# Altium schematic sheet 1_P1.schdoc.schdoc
size 309 x 223 mm; Symbol: Sheet-Symbol_A4; Device: Sheet-Symbol_A4; Company: ROMASZEWSKI; Drawed: ROMASZEWSKI; Reviewed: EasyEDA Pro; Version: V0.1; Page Size: A4; @Project Name: stm32wb5mmg01; @Page Count: 1; @Update Date: 2023-11-05; @Create Date: 2023-10-26; @Schematic Name: Shield MB STM32WB55; Part Number: JLCPCB-002; @Page No: 1; @Page Name: P1
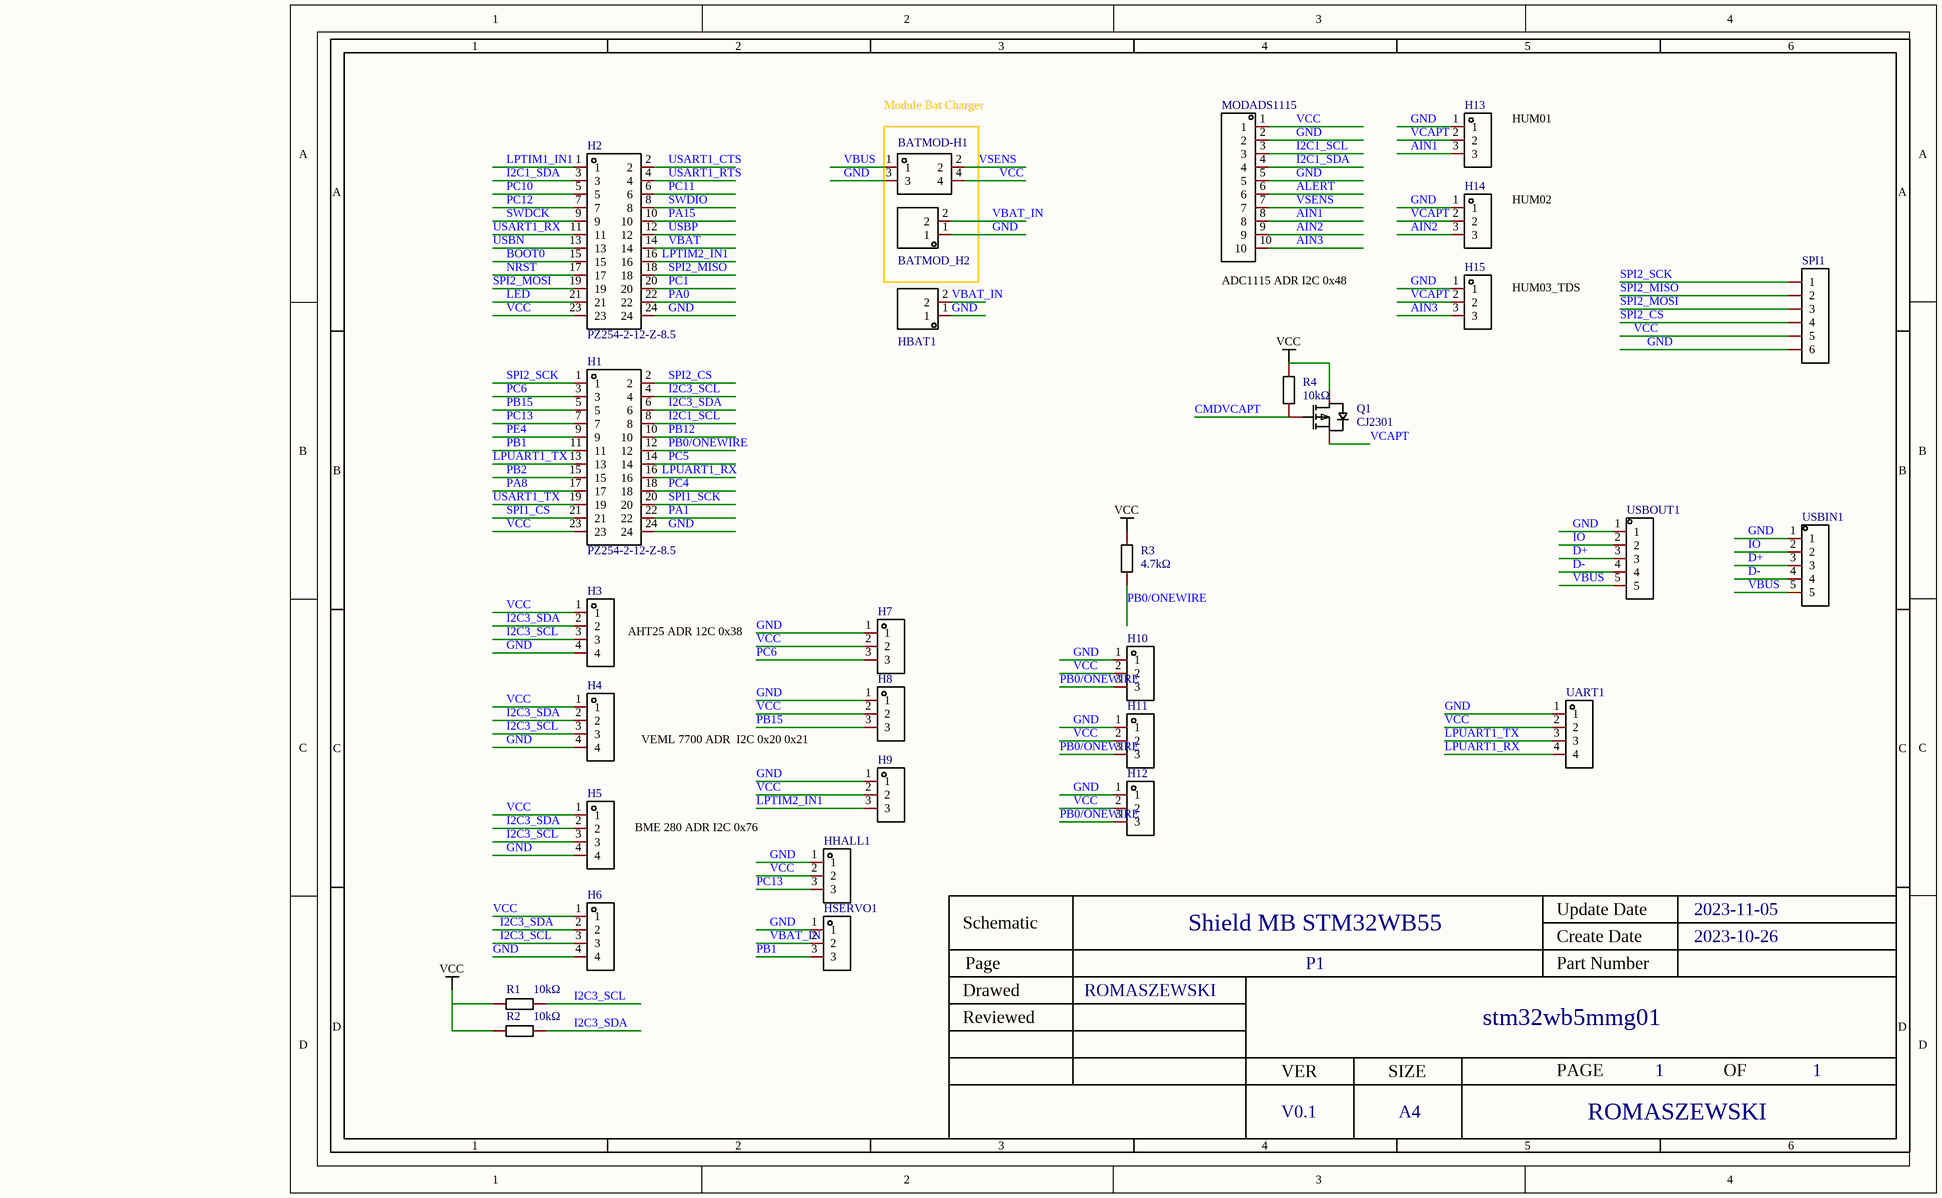
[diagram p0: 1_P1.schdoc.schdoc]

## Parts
BATMOD-H1  HDR-M_2.54_2x2  [HDR-TH_4P-P2.54-V-M-R2-C2-S2.54-1]  (value not drawn)
BATMOD_H2  HDR-M_2.54_1x2P  [HDR-TH_2P-P2.54-V-M-1]  (value not drawn)
H1  PZ254-2-12-Z-8.5  [HDR-TH_24P-P2.54-V-M-R2-C12-S2.54]
H2  PZ254-2-12-Z-8.5  [HDR-TH_24P-P2.54-V-M-R2-C12-S2.54]
H3  HDR-M_2.54_1x4P  [HDR-TH_4P-P2.54-V-M]  (value not drawn)
H4  HDR-M_2.54_1x4P  [HDR-TH_4P-P2.54-V-M]  (value not drawn)
H5  HDR-M_2.54_1x4P  [HDR-TH_4P-P2.54-V-M]  (value not drawn)
H6  HDR-M_2.54_1x4P  [HDR-TH_4P-P2.54-V-M]  (value not drawn)
H7  HDR-M_2.54_1x3P  [HDR-TH_3P-P2.54-V-M]  (value not drawn)
H8  HDR-M_2.54_1x3P  [HDR-TH_3P-P2.54-V-M]  (value not drawn)
H9  HDR-M_2.54_1x3P  [HDR-TH_3P-P2.54-V-M]  (value not drawn)
H10  HDR-M_2.54_1x3P  [HDR-TH_3P-P2.54-V-M]  (value not drawn)
H11  HDR-M_2.54_1x3P  [HDR-TH_3P-P2.54-V-M]  (value not drawn)
H12  HDR-M_2.54_1x3P  [HDR-TH_3P-P2.54-V-M]  (value not drawn)
H13  HDR-M_2.54_1x3P  [HDR-TH_3P-P2.54-V-M]  (value not drawn)
H14  HDR-M_2.54_1x3P  [HDR-TH_3P-P2.54-V-M]  (value not drawn)
H15  HDR-M_2.54_1x3P  [HDR-TH_3P-P2.54-V-M]  (value not drawn)
HBAT1  HDR-M_2.54_1x2P  [HDR-TH_2P-P2.54-V-M-1]  (value not drawn)
HHALL1  HDR-M_2.54_1x3P  [HDR-TH_3P-P2.54-V-M]  (value not drawn)
HSERVO1  HDR-M_2.54_1x3P  [HDR-TH_3P-P2.54-V-M]  (value not drawn)
MODADS1115  HDR-M_2.54_1x10P  [HDR-TH_10P-P2.54-V-M-1]  (value not drawn)
Q1  CJ2301  [SOT-23-3_L2.9-W1.3-P1.90-LS2.4-BR]
R1  10kΩ  [R1206]
R2  10kΩ  [R1206]
R3  4.7kΩ  [R1206]
R4  10kΩ  [R1206]
SPI1  HDR-M_2.54_1x6P  [HDR-TH_6P-P2.54-V-M-1]  (value not drawn)
UART1  HDR-M_2.54_1x4P  [HDR-TH_4P-P2.54-V-M]  (value not drawn)
USBIN1  HDR-M_2.54_1x5P  [HDR-TH_5P-P2.54-V-M]  (value not drawn)
USBOUT1  HDR-M_2.54_1x5P  [HDR-TH_5P-P2.54-V-M]  (value not drawn)

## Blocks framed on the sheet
Module Bat Charger: BATMOD-H1 BATMOD_H2

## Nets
VCC: BATMOD-H1.4 H1.23 H2.23 H3.1 H4.1 H5.1 H6.1 H7.2 H8.2 H9.2 H10.2 H11.2 H12.2 HHALL1.2 MODADS1115.1 Q1.3(D) R1.1 R2.1 R3.2 R4.2 SPI1.5 UART1.2
AIN1: H13.3 MODADS1115.8
AIN2: H14.3 MODADS1115.9
AIN3: H15.3 MODADS1115.10
ALERT: MODADS1115.6
BOOT0: H2.15
CMDVCAPT: Q1.1(G) R4.1
D+: USBIN1.3 USBOUT1.3
D-: USBIN1.4 USBOUT1.4
GND: BATMOD-H1.3 BATMOD_H2.1 H1.24 H2.24 H3.4 H4.4 H5.4 H6.4 H7.1 H8.1 H9.1 H10.1 H11.1 H12.1 H13.1 H14.1 H15.1 HBAT1.1 HHALL1.1 HSERVO1.1 MODADS1115.2 MODADS1115.5 SPI1.6 UART1.1 USBIN1.1 USBOUT1.1
I2C1_SCL: H1.8 MODADS1115.3
I2C1_SDA: H2.3 MODADS1115.4
I2C3_SCL: H1.4 H3.3 H4.3 H5.3 H6.3 R1.2
I2C3_SDA: H1.6 H3.2 H4.2 H5.2 H6.2 R2.2
IO: USBIN1.2 USBOUT1.2
LED: H2.21
LPTIM1_IN1: H2.1
LPTIM2_IN1: H2.16 H9.3
LPUART1_RX: H1.16 UART1.4
LPUART1_TX: H1.13 UART1.3
NRST: H2.17
PA0: H2.22
PA1: H1.22
PA8: H1.17
PA15: H2.10
PB0/ONEWIRE: H1.12 H10.3 H11.3 H12.3 R3.1
PB1: H1.11 HSERVO1.3
PB2: H1.15
PB12: H1.10
PB15: H1.5 H8.3
PC1: H2.20
PC4: H1.18
PC5: H1.14
PC6: H1.3 H7.3
PC10: H2.5
PC11: H2.6
PC12: H2.7
PC13: H1.7 HHALL1.3
PE4: H1.9
SPI1_CS: H1.21
SPI1_SCK: H1.20
SPI2_CS: H1.2 SPI1.4
SPI2_MISO: H2.18 SPI1.2
SPI2_MOSI: H2.19 SPI1.3
SPI2_SCK: H1.1 SPI1.1
SWDCK: H2.9
SWDIO: H2.8
USART1_CTS: H2.2
USART1_RTS: H2.4
USART1_RX: H2.11
USART1_TX: H1.19
USBN: H2.13
USBP: H2.12
VBAT: H2.14
VBAT_IN: BATMOD_H2.2 HBAT1.2 HSERVO1.2
VBUS: BATMOD-H1.1 USBIN1.5 USBOUT1.5
VCAPT: H13.2 H14.2 H15.2 Q1.2(S)
VSENS: BATMOD-H1.2 MODADS1115.7

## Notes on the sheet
- (near H13) HUM01
- HUM02
- (near MODADS1115) ADC1115 ADR I2C 0x48
- HUM03_TDS
- (near H3) AHT25 ADR 12C 0x38
- VEML 7700 ADR  I2C 0x20 0x21
- BME 280 ADR I2C 0x76

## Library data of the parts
BATMOD-H1 = HDR-M_2.54_2x2: Symbol: HDR-M-2.54_2x2; Add into BOM: no; Convert to PCB: yes
BATMOD_H2 HBAT1 = HDR-M_2.54_1x2P: Symbol: 210S-1*2P L=11.6MMGold-plated black; Convert to PCB: yes; Add into BOM: no
H1 H2 = PZ254-2-12-Z-8.5: Manufacturer: HCTL(华灿天禄); Add into BOM: yes; Pitch: 2.54mm; Pin Structure: 2x12P; Circluar Pins/Square Pins: Square Pins; Current Rating (Max): 3A; Description: Number of Rows:双排 Number of Pins:24P Pitch:2.54mm Pin Structure:2x12P Row Spacing:2.54mm Mounting Type:Straight Circluar Pins/Square Pins:Square Pins Current Rating (Max):3A Voltage Rating (Max):- Length of Mating Pin:6mm Insulation Height:2.5mm Length of
H3-H6 UART1 = HDR-M_2.54_1x4P: Manufacturer: XFCN(兴飞); Symbol: PZ254V-11-04P; Convert to PCB: yes
H7-H15 HHALL1 HSERVO1 = HDR-M_2.54_1x3P: Symbol: PZ254V-11-03P_C2937625; Convert to PCB: yes
MODADS1115 = HDR-M_2.54_1x10P: Symbol: Header-Male-2.54_1x10; Convert to PCB: yes
Q1 = CJ2301: Manufacturer: CJ(江苏长电/长晶); Add into BOM: yes; Power Dissipation (Pd): 0.4W; Drain Source On Resistance (RDS(on)@Vgs,Id): 0.09Ω@4.5V,2.8A; Gate Threshold Voltage (Vgs(th)@Id): 0.7V@250uA; Total Gate Charge (Qg@Vgs): 3.3nC@4.5V; Input Capacitance (Ciss@Vds): 405pF@10V; Reverse Transfer Capacitance (Crss@Vds): 55pF@10V; Description: Type: Drain Source Voltage (Vdss): Continuous Drain Current (Id): Power Dissipation (Pd):0.4W Drain Source On Resistance (RDS(on)@Vgs,Id):0.09Ω@4.5V,2.8A Gate Threshold Voltage (Vgs(th)@Id):0.7V@250uA Total Gate Charge (Qg@Vgs):3.3nC@4.5V Input Capacitanc
R1-R4 = Res_1206: Symbol: Res; Add into BOM: yes
SPI1 = HDR-M_2.54_1x6P: Symbol: Header-Male-2.54_1x6; Convert to PCB: yes
USBIN1 USBOUT1 = HDR-M_2.54_1x5P: Symbol: MTP125-1105S1; Convert to PCB: yes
